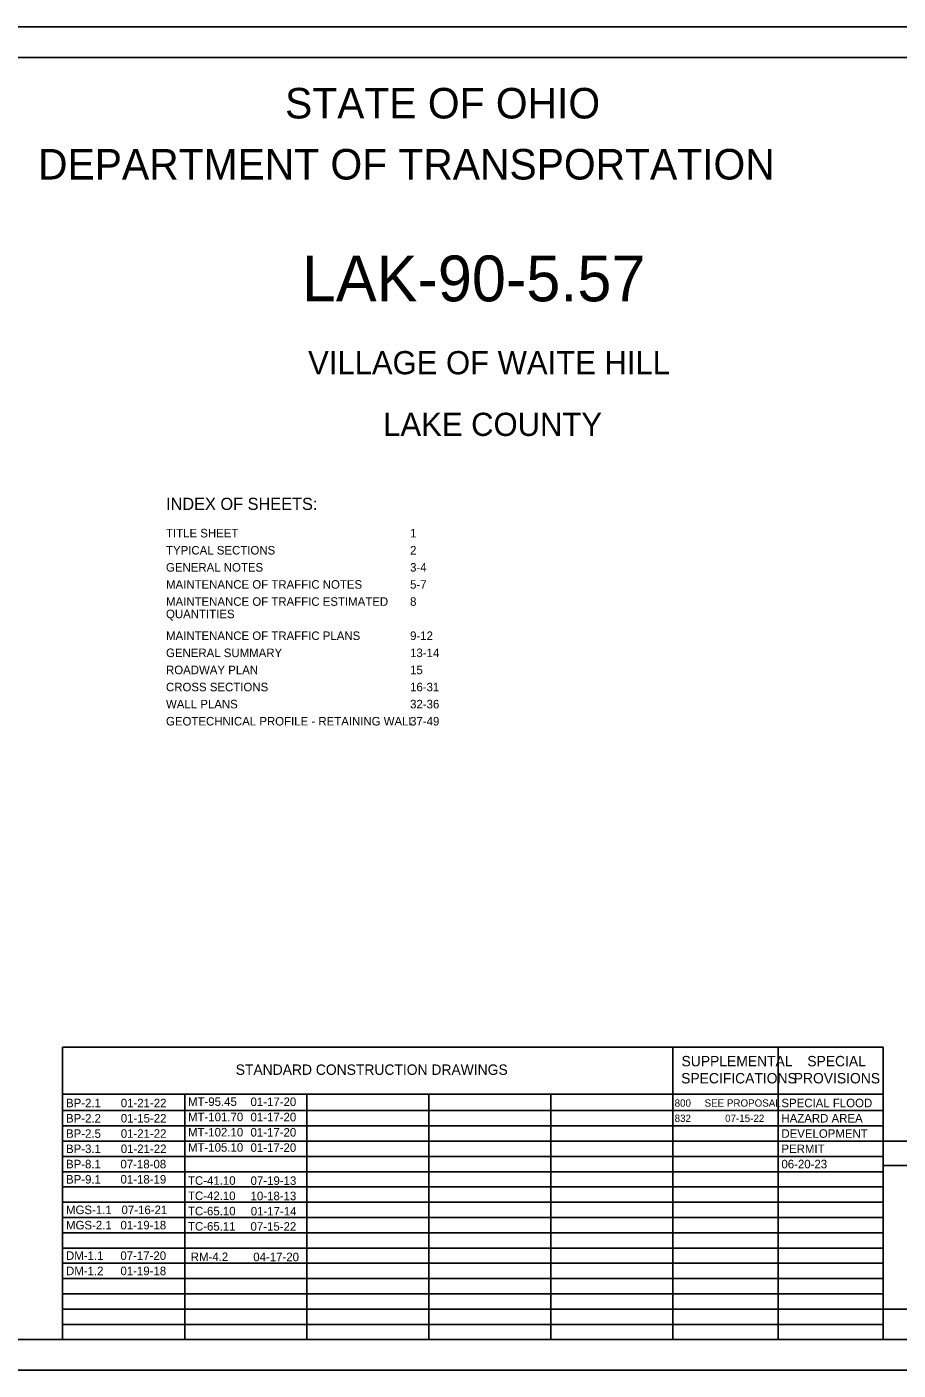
# Model space of a CAD drawing. Extents: x 0 to 44.3, y 0 to 22.
# Drawn here: x 9.56 to 23.84, y 0 to 22 of the extents above; entities that cross this region are included whole.
import ezdxf

# ---------------------------------------------------------------- set-up
doc = ezdxf.new("R2010")
doc.units = 0
for name, color, linetype in [('SH_Border', 7, 'Continuous'), ('SH_Cut_Line', 7, 'Continuous'), ('SH_Data', 7, 'Continuous'), ('SH_Text', 7, 'Continuous')]:
    doc.layers.add(name, color=color, linetype=linetype)

msp = doc.modelspace()

# ---------------------------------------------------------------- linework, layer by layer
at = {"layer": 'SH_Border'}
msp.add_lwpolyline([(1.5, 21.5), (33.5, 21.5), (33.5, 0.5), (1.5, 0.5)], close=True, dxfattribs=at)
at = {"layer": 'SH_Cut_Line'}
for points in [[(0, 0), (34, 0), (34, 22), (0, 22)], [(0, 22), (34, 22), (34, 0), (0, 0)]]:
    msp.add_lwpolyline(points, close=True, dxfattribs=at)
at = {"layer": 'SH_Data'}
for p, q in [((10.15, 5.292), (23.6, 5.292)), ((10.15, 0.5), (10.15, 5.292)), ((20.15, 0.5), (20.15, 5.292)), ((21.875, 0.5), (21.875, 5.292)), ((23.6, 0.5), (23.6, 5.292)), ((10.15, 4.521), (23.6, 4.521)), ((12.15, 0.5), (12.15, 4.521)), ((14.15, 0.5), (14.15, 4.521)), ((16.15, 0.5), (16.15, 4.521)), ((18.15, 0.5), (18.15, 4.521)), ((10.15, 4.25), (23.6, 4.25)), ((10.15, 4), (23.6, 4)), ((10.15, 3.75), (23.6, 3.75)), ((26.4, 3.75), (23.6, 3.75)), ((23.6, 3.75), (23.6, 0.5)), ((10.15, 3.5), (23.6, 3.5)), ((26.4, 3.35), (23.6, 3.35)), ((10.15, 3.25), (23.6, 3.25)), ((10.15, 3), (23.6, 3)), ((10.15, 2.75), (23.6, 2.75)), ((10.15, 2.5), (23.6, 2.5)), ((10.15, 2.25), (23.6, 2.25)), ((10.15, 2), (23.6, 2)), ((10.15, 1.75), (23.6, 1.75)), ((10.15, 1.5), (23.6, 1.5)), ((10.15, 1.25), (23.6, 1.25)), ((10.15, 1), (23.6, 1)), ((10.15, 0.75), (23.6, 0.75)), ((26.4, 0.5), (23.6, 0.5))]:
    msp.add_line(p, q, dxfattribs=at)
msp.add_lwpolyline([(26.4, 0.5), (26.4, 1), (23.6, 1), (23.6, 0.5)], close=True, dxfattribs=at)

# ---------------------------------------------------------------- texts
at = {"layer": 'SH_Text'}
for s, height, p in [('STATE OF OHIO', 0.5, (13.795, 20.5)), ('DEPARTMENT OF TRANSPORTATION', 0.5, (9.747, 19.5)), (' LAK-90-5.57', 0.75, (13.791, 17.505)), ('VILLAGE OF WAITE HILL', 0.38, (14.173, 16.31)), ('     LAKE COUNTY    ', 0.38, (14.698, 15.3)), ('INDEX OF SHEETS:', 0.2, (11.844, 14.088)), ('INDEX OF SHEETS:', 0.2, (11.844, 14.088)), ('TITLE SHEET                        ', 0.14, (11.844, 13.638)), ('1      ', 0.14, (15.844, 13.638)), ('TYPICAL SECTIONS                   ', 0.14, (11.844, 13.358)), ('2      ', 0.14, (15.844, 13.358)), ('GENERAL NOTES                      ', 0.14, (11.844, 13.078)), ('3-4    ', 0.14, (15.844, 13.078)), ('MAINTENANCE OF TRAFFIC NOTES       ', 0.14, (11.844, 12.798)), ('5-7    ', 0.14, (15.844, 12.798)), ('MAINTENANCE OF TRAFFIC ESTIMATED ', 0.14, (11.844, 12.518)), ('8      ', 0.14, (15.844, 12.518)), ('QUANTITIES', 0.14, (11.844, 12.315)), ('MAINTENANCE OF TRAFFIC PLANS       ', 0.14, (11.844, 11.958)), ('9-12   ', 0.14, (15.844, 11.958)), ('GENERAL SUMMARY                    ', 0.14, (11.844, 11.678)), ('13-14  ', 0.14, (15.844, 11.678)), ('ROADWAY PLAN                       ', 0.14, (11.844, 11.398)), ('15     ', 0.14, (15.844, 11.398)), ('CROSS SECTIONS                     ', 0.14, (11.844, 11.118)), ('16-31  ', 0.14, (15.844, 11.118)), ('WALL PLANS                         ', 0.14, (11.844, 10.838)), ('32-36  ', 0.14, (15.844, 10.838)), ('GEOTECHNICAL PROFILE - RETAINING WALL   ', 0.14, (11.844, 10.558)), ('37-49  ', 0.14, (15.844, 10.558)), ('SUPPLEMENTAL', 0.17, (20.293, 4.976)), ('SPECIAL', 0.17, (22.354, 4.976)), ('STANDARD CONSTRUCTION DRAWINGS', 0.17, (12.986, 4.836)), ('SPECIFICATIONS', 0.17, (20.287, 4.696)), ('PROVISIONS', 0.17, (22.132, 4.696)), ('BP-2.1   ', 0.14, (10.205, 4.305)), ('01-21-22', 0.14, (11.102, 4.305)), ('MT-95.45', 0.14, (12.204, 4.327)), ('01-17-20', 0.14, (13.229, 4.325)), ('800     SEE PROPOSAL', 0.12, (20.18, 4.315)), ('SPECIAL FLOOD  ', 0.14, (21.93, 4.305)), ('BP-2.2   ', 0.14, (10.205, 4.055)), ('01-15-22', 0.14, (11.102, 4.055)), ('MT-101.70', 0.14, (12.204, 4.077)), ('01-17-20', 0.14, (13.229, 4.075)), ('832            ', 0.12, (20.18, 4.065)), ('       07-15-22', 0.12, (20.695, 4.065)), ('HAZARD AREA    ', 0.14, (21.93, 4.055)), ('MT-102.10', 0.14, (12.204, 3.827)), ('01-17-20', 0.14, (13.229, 3.825)), ('BP-2.5   ', 0.14, (10.205, 3.805)), ('01-21-22', 0.14, (11.102, 3.805)), ('DEVELOPMENT                   ', 0.14, (21.93, 3.805)), ('BP-3.1   ', 0.14, (10.205, 3.555)), ('01-21-22', 0.14, (11.102, 3.555)), ('MT-105.10', 0.14, (12.204, 3.577)), ('01-17-20', 0.14, (13.229, 3.575)), ('PERMIT         ', 0.14, (21.93, 3.555)), ('BP-8.1   ', 0.14, (10.205, 3.305)), ('07-18-08', 0.14, (11.097, 3.305)), ('06-20-23       ', 0.14, (21.93, 3.305)), ('BP-9.1   ', 0.14, (10.205, 3.055)), ('01-18-19', 0.14, (11.098, 3.055)), ('TC-41.10', 0.14, (12.204, 3.035)), ('07-19-13', 0.14, (13.23, 3.033)), ('TC-42.10', 0.14, (12.204, 2.785)), ('10-18-13', 0.14, (13.23, 2.783)), ('MGS-1.1  ', 0.14, (10.205, 2.555)), ('07-16-21', 0.14, (11.115, 2.555)), ('TC-65.10', 0.14, (12.204, 2.535)), ('01-17-14', 0.14, (13.233, 2.533)), ('MGS-2.1  ', 0.14, (10.205, 2.305)), ('01-19-18', 0.14, (11.097, 2.305)), ('TC-65.11', 0.14, (12.204, 2.285)), ('07-15-22', 0.14, (13.229, 2.283)), ('DM-1.1   ', 0.14, (10.205, 1.805)), ('07-17-20', 0.14, (11.096, 1.805)), ('RM-4.2', 0.14, (12.249, 1.786)), ('04-17-20', 0.14, (13.274, 1.784)), ('DM-1.2   ', 0.14, (10.205, 1.555)), ('01-19-18', 0.14, (11.097, 1.555))]:
    msp.add_text(s, height=height, dxfattribs=at).set_placement(p)

doc.saveas('drawing.dxf')
